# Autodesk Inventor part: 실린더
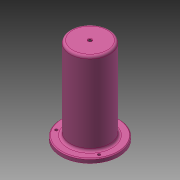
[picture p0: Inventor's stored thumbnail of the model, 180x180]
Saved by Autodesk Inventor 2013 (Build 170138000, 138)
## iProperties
Created: 2017-05
Part Number: 실린더
Material: 알루미늄 6061
Document SubType Name: Modeling
Designer: mduedu
Density: 2.71 g/cm^3
Mass: 201.817 g
Surface Area: 358.986 cm^2
Volume: 74.4712 cm^3
Author: mduedu
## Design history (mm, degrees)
sketch "스케치1"
  geometry: C1 r 35 at (0, 0); 1 further point
  constraints: 1 centre point, 1 coincident
  dimensions: "d0" = 70 diameter of C1
extrude "돌출1" new body sketch "스케치1" distance "d1" = 5; taper "d2" = 0 deg
sketch "스케치2"
  geometry: C1 r 24 at (0, 0); 1 further point
  constraints: 1 centre point, 1 coincident
  dimensions: "d3" = 48 diameter of C1
extrude "돌출2" join sketch "스케치2" distance "d4" = 100; taper "d5" = 0 deg
sketch "스케치3"
  geometry: C1 r 20 at (0, 0); 1 further point
  constraints: 1 centre point, 1 coincident
  dimensions: "d6" = 40 diameter of C1
extrude "돌출3" cut sketch "스케치3" distance "d7" = 100; taper "d8" = 0 deg
chamfer "모따기1" distance "d9" = 1; stored, may be unused: second distance "d10" = 2, angle "d11" = 45 deg
fillet "모깎기1" dims "d12" = 3
sketch "스케치5" dims "d16" = 60
  geometry: C1 r 35 at (0, 0) reference; 5 further points
  constraints: 2 vertical alignment, 1 coincident, 6 other
  dimensions: "d20" = 360 deg dimension on point (0, 0) point (0, 30) (derived)
sketch "스케치6"
  geometry: 3 further points
  constraints: 3 other
hole "구멍1" sketch "스케치6" at (-25.981, -15), (25.981, -15), (0, 30) diameter "d22" = 3.4; stored, may be unused: countersink angle "d26" = 90 deg, drill point angle "d28" = 0 deg; dims "d23" = 6, "d24" = 4, "d25" = 2, "d27" = 8
hole "구멍3" diameter "d34" = 4.134; stored, may be unused: countersink angle "d38" = 90 deg, drill point angle "d40" = 118 deg; dims "d32" = 10, "d33" = 10, "d35" = 6, "d36" = 4, "d37" = 2, "d39" = 8
chamfer "모따기2" distance "d41" = 0.5; stored, may be unused: second distance "d42" = 2, angle "d43" = 45 deg
node "솔리드1"
